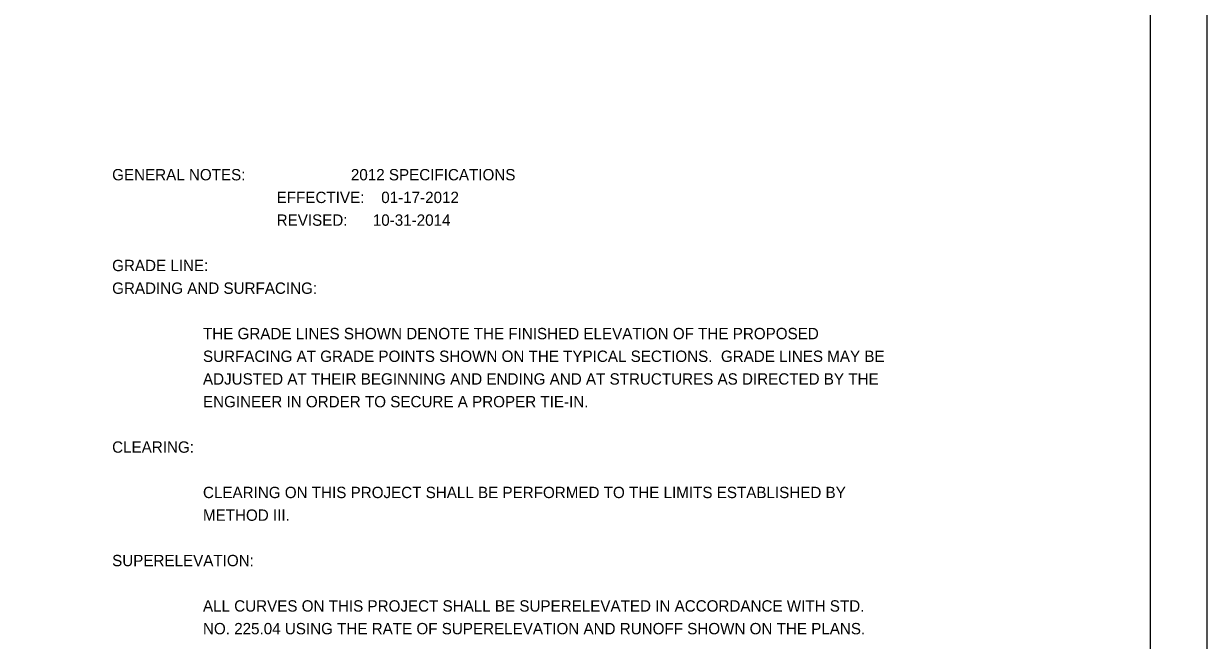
# Model space of a CAD drawing. Extents: x 972 to 1006, y 10585.8 to 10607.8.
# Drawn here: x 995.56 to 1005.99, y 10596.92 to 10602.35 of the extents above; entities that cross this region are included whole.
import ezdxf

# ---------------------------------------------------------------- set-up
doc = ezdxf.new("R2010")
doc.units = 0
for name, color, linetype in [('Sheet Data Text CELL', 7, 'Continuous'), ('Sheet Plan CELL', 7, 'Continuous'), ('Stewart Plot Border Xerox6279 and LJ5000', 7, 'Continuous')]:
    doc.layers.add(name, color=color, linetype=linetype)

msp = doc.modelspace()

# ---------------------------------------------------------------- linework, layer by layer
at = {"layer": 'Sheet Plan CELL'}
msp.add_lwpolyline([(1005.487, 10607.285), (975.487, 10607.285), (975.487, 10586.285), (1005.487, 10586.285)], close=True, dxfattribs=at)
at = {"layer": 'Stewart Plot Border Xerox6279 and LJ5000'}
msp.add_lwpolyline([(971.987, 10585.785), (1005.987, 10585.785), (1005.987, 10607.785), (971.987, 10607.785)], close=True, dxfattribs=at)

# ---------------------------------------------------------------- texts
at = {"layer": 'Sheet Data Text CELL'}
for s, p in [('GENERAL NOTES:                         2012 SPECIFICATIONS', (996.341, 10600.97)), ('                                       EFFECTIVE:    01-17-2012', (996.341, 10600.77)), ('                                       REVISED:      10-31-2014', (996.341, 10600.57)), ('GRADE LINE:  ', (996.341, 10600.17)), ('GRADING AND SURFACING:  ', (996.341, 10599.97)), ('THE GRADE LINES SHOWN DENOTE THE FINISHED ELEVATION OF THE PROPOSED ', (997.141, 10599.57)), ('SURFACING AT GRADE POINTS SHOWN ON THE TYPICAL SECTIONS.  GRADE LINES MAY BE ', (997.141, 10599.37)), ('ADJUSTED AT THEIR BEGINNING AND ENDING AND AT STRUCTURES AS DIRECTED BY THE ', (997.141, 10599.17)), ('ENGINEER IN ORDER TO SECURE A PROPER TIE-IN.  ', (997.141, 10598.97)), ('CLEARING:  ', (996.341, 10598.57)), ('CLEARING ON THIS PROJECT SHALL BE PERFORMED TO THE LIMITS ESTABLISHED BY ', (997.141, 10598.17)), ('METHOD III.', (997.141, 10597.97)), ('SUPERELEVATION:  ', (996.341, 10597.57)), ('ALL CURVES ON THIS PROJECT SHALL BE SUPERELEVATED IN ACCORDANCE WITH STD. ', (997.141, 10597.17)), ('NO. 225.04 USING THE RATE OF SUPERELEVATION AND RUNOFF SHOWN ON THE PLANS.', (997.141, 10596.97))]:
    msp.add_text(s, height=0.1, dxfattribs=at).set_placement(p)

doc.saveas('drawing.dxf')
